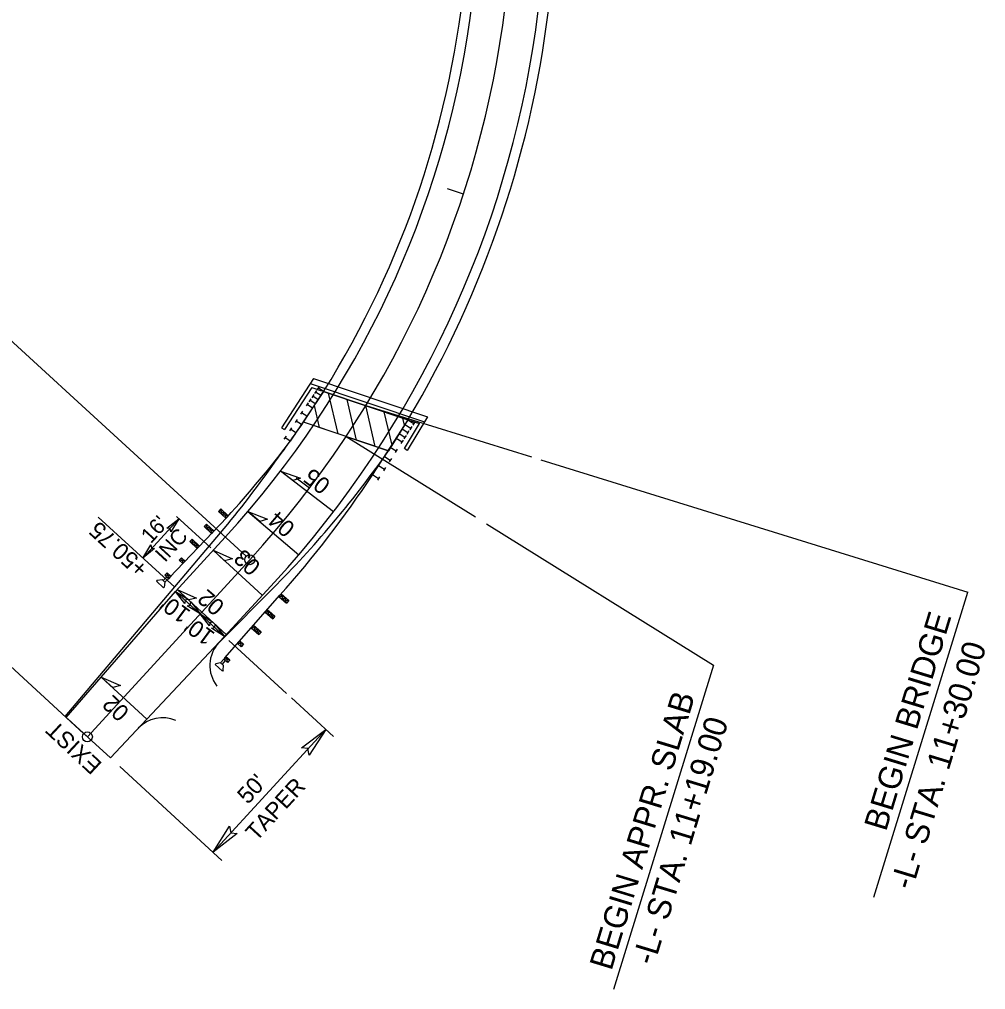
# Model space of a CAD drawing. Extents: x 1348352 to 1349119, y 1028998 to 1029749.
# Drawn here: x 1348729 to 1349018.8, y 1028998.5 to 1029289.4 of the extents above; entities that cross this region are included whole.
import ezdxf

# ---------------------------------------------------------------- set-up
doc = ezdxf.new("R2010")
doc.units = 0
for name, color, linetype in [('Default', 7, 'Continuous'), ('Prop Dimension', 7, 'Continuous'), ('Prop Dimension Text', 7, 'Continuous'), ('Prop DSN Text', 7, 'Continuous'), ('Prop EOT', 7, 'Continuous'), ('Prop Guardrail', 7, 'Continuous'), ('Prop Guardrail Anchor Unit CELL', 7, 'Continuous'), ('Prop Horizontal Alignment', 7, 'Continuous'), ('Prop Horizontal Alignment Station Label', 7, 'Continuous'), ('Prop Horizontal Alignment Tick Large', 7, 'Continuous'), ('Prop Horizontal Alignment Tick Small', 7, 'Continuous'), ('Prop Leader Line Medium', 7, 'Continuous'), ('Prop Paved Shoulder', 7, 'Continuous'), ('Prop Roadway Bridge', 7, 'Continuous'), ('Prop Structure Anchor Unit CELL', 7, 'Continuous'), ('Prop Superelevation  Arrow CELL', 7, 'Continuous'), ('Prop Superelevation Label', 7, 'Continuous'), ('Prop Terminator CELL', 7, 'Continuous')]:
    doc.layers.add(name, color=color, linetype=linetype)

msp = doc.modelspace()

# ---------------------------------------------------------------- linework, layer by layer
at = {"layer": 'Default'}
for p, q in [((1348817.21, 1029181.75), (1348807.64, 1029166.96)), ((1348816.65, 1029179.04), (1348808.46, 1029166.38)), ((1348851.42, 1029170.26), (1348845.3, 1029160.18)), ((1348844.44, 1029160.7), (1348848.99, 1029168.18)), ((1348807.64, 1029166.96), (1348808.46, 1029166.38)), ((1348845.3, 1029160.18), (1348844.44, 1029160.7))]:
    msp.add_line(p, q, dxfattribs=at)
for points in [[(1348817.21, 1029181.75), (1348851.42, 1029170.26)], [(1348816.23, 1029180.24), (1348850.49, 1029168.73)], [(1348816.23, 1029180.24), (1348850.49, 1029168.73)], [(1348816.65, 1029179.04), (1348819.57, 1029178.06)], [(1348845.51, 1029169.35), (1348848.99, 1029168.18)]]:
    msp.add_lwpolyline(points, dxfattribs=at)
at = {"layer": 'Prop Dimension'}
for p, q in [((1348775.56, 1029119.11), (1348752.6, 1029140.17)), ((1348776.79, 1029139.69), (1348765.98, 1029127.9)), ((1348776.06, 1029140.37), (1348786.38, 1029130.9)), ((1348790.53, 1029104.37), (1348775.79, 1029117.88)), ((1348809.12, 1029087.32), (1348791.84, 1029103.17)), ((1348823.22, 1029074.39), (1348810.6, 1029085.96)), ((1348787.09, 1029039.68), (1348820.88, 1029076.53)), ((1348789.75, 1029037.24), (1348759.1, 1029065.35))]:
    msp.add_line(p, q, dxfattribs=at)
at = {"layer": 'Prop EOT'}
for p, q in [((1348775.79, 1029117.88), (1348790.71, 1029134.15)), ((1348790.53, 1029104.37), (1348805.45, 1029120.64)), ((1348743.04, 1029080.07), (1348775.79, 1029117.88)), ((1348756.28, 1029067.94), (1348790.53, 1029104.37)), ((1348756.28, 1029067.94), (1348743.04, 1029080.07))]:
    msp.add_line(p, q, dxfattribs=at)
for centre, radius, start, end in [((1348576.98, 1029330.16), 310, 317.4777, 26.2288), ((1348576.98, 1029330.16), 290, 317.4777, 26.2288), ((1348796.1, 1029095.69), 10, 136.7575, 218.2791), ((1348771.93, 1029069.99), 10, 66.6994, 136.7575)]:
    msp.add_arc(centre, radius, start, end, dxfattribs=at)
at = {"layer": 'Prop Guardrail'}
for centre, radius, start, end in [((1348579.88, 1029335.52), 287.83, 317.2565, 323.1599), ((1348572.34, 1029326.1), 314.58, 318.2785, 326.5917)]:
    msp.add_arc(centre, radius, start, end, dxfattribs=at)
at = {"layer": 'Prop Guardrail Anchor Unit CELL'}
for p, q in [((1348789.41, 1029142.62), (1348788.72, 1029141.89)), ((1348790.92, 1029139.8), (1348788.72, 1029141.89)), ((1348788.72, 1029141.89), (1348790.51, 1029141.57)), ((1348791.61, 1029140.52), (1348789.41, 1029142.62)), ((1348789.82, 1029140.85), (1348789.41, 1029142.62)), ((1348790.51, 1029141.57), (1348789.82, 1029140.85)), ((1348790.51, 1029141.57), (1348790.92, 1029139.8)), ((1348774.02, 1029122.06), (1348791.26, 1029140.16)), ((1348785.1, 1029138.09), (1348784.41, 1029137.37)), ((1348787.3, 1029136), (1348785.1, 1029138.09)), ((1348785.51, 1029136.32), (1348785.1, 1029138.09)), ((1348791.61, 1029140.52), (1348789.82, 1029140.85)), ((1348791.61, 1029140.52), (1348790.92, 1029139.8)), ((1348786.61, 1029135.27), (1348784.41, 1029137.37)), ((1348784.41, 1029137.37), (1348786.2, 1029137.04)), ((1348786.2, 1029137.04), (1348785.51, 1029136.32)), ((1348787.3, 1029136), (1348785.51, 1029136.32)), ((1348786.2, 1029137.04), (1348786.61, 1029135.27)), ((1348787.3, 1029136), (1348786.61, 1029135.27)), ((1348780.79, 1029133.56), (1348780.1, 1029132.84)), ((1348782.3, 1029130.75), (1348780.1, 1029132.84)), ((1348780.1, 1029132.84), (1348781.89, 1029132.52)), ((1348782.99, 1029131.47), (1348780.79, 1029133.56)), ((1348781.2, 1029131.79), (1348780.79, 1029133.56)), ((1348781.89, 1029132.52), (1348781.2, 1029131.79)), ((1348781.89, 1029132.52), (1348782.3, 1029130.75)), ((1348782.99, 1029131.47), (1348781.2, 1029131.79)), ((1348782.99, 1029131.47), (1348782.3, 1029130.75)), ((1348777.58, 1029127.99), (1348776.89, 1029127.27)), ((1348777.99, 1029126.22), (1348776.89, 1029127.27)), ((1348778.68, 1029126.94), (1348776.89, 1029127.27)), ((1348778.68, 1029126.94), (1348777.58, 1029127.99)), ((1348777.58, 1029127.99), (1348777.99, 1029126.22)), ((1348778.68, 1029126.94), (1348777.99, 1029126.22)), ((1348773.27, 1029123.47), (1348772.58, 1029122.74)), ((1348774.37, 1029122.42), (1348773.27, 1029123.47)), ((1348773.27, 1029123.46), (1348773.68, 1029121.69)), ((1348770.34, 1029121.22), (1348770.13, 1029121)), ((1348772.25, 1029118.97), (1348770.13, 1029121)), ((1348770.34, 1029121.22), (1348771.77, 1029121.48)), ((1348771.77, 1029121.48), (1348772.65, 1029120.64)), ((1348772.13, 1029121.13), (1348773.15, 1029122.2)), ((1348772.65, 1029120.64), (1348772.46, 1029119.19)), ((1348773.68, 1029121.69), (1348772.58, 1029122.74)), ((1348774.37, 1029122.42), (1348772.58, 1029122.74)), ((1348773.67, 1029121.7), (1348772.65, 1029120.64)), ((1348774.37, 1029122.42), (1348773.68, 1029121.69)), ((1348772.46, 1029119.19), (1348772.25, 1029118.97)), ((1348790.61, 1029097.98), (1348807.14, 1029116.74)), ((1348807.47, 1029117.12), (1348806.81, 1029116.37)), ((1348806.81, 1029116.37), (1348809.09, 1029114.36)), ((1348808.61, 1029116.11), (1348806.81, 1029116.37)), ((1348807.47, 1029117.12), (1348809.75, 1029115.11)), ((1348807.47, 1029117.12), (1348807.95, 1029115.36)), ((1348808.61, 1029116.11), (1348807.95, 1029115.36)), ((1348807.95, 1029115.36), (1348809.75, 1029115.11)), ((1348809.09, 1029114.36), (1348808.61, 1029116.11)), ((1348809.75, 1029115.11), (1348809.09, 1029114.36)), ((1348803.34, 1029112.43), (1348802.68, 1029111.68)), ((1348803.34, 1029112.43), (1348805.62, 1029110.42)), ((1348803.34, 1029112.43), (1348803.82, 1029110.67)), ((1348802.68, 1029111.68), (1348804.96, 1029109.67)), ((1348804.48, 1029111.42), (1348802.68, 1029111.68)), ((1348804.48, 1029111.42), (1348803.82, 1029110.67)), ((1348803.82, 1029110.67), (1348805.62, 1029110.42)), ((1348804.96, 1029109.67), (1348804.48, 1029111.42)), ((1348805.62, 1029110.42), (1348804.96, 1029109.67)), ((1348799.21, 1029107.74), (1348798.55, 1029106.99)), ((1348798.55, 1029106.99), (1348800.82, 1029104.98)), ((1348800.35, 1029106.73), (1348798.55, 1029106.99)), ((1348799.21, 1029107.74), (1348801.48, 1029105.73)), ((1348799.21, 1029107.74), (1348799.68, 1029105.98)), ((1348800.35, 1029106.73), (1348799.68, 1029105.98)), ((1348799.68, 1029105.98), (1348801.48, 1029105.73)), ((1348800.82, 1029104.98), (1348800.35, 1029106.73)), ((1348801.48, 1029105.73), (1348800.82, 1029104.98)), ((1348795.08, 1029103.05), (1348794.41, 1029102.3)), ((1348794.41, 1029102.3), (1348795.55, 1029101.29)), ((1348796.21, 1029102.04), (1348794.41, 1029102.3)), ((1348795.08, 1029103.05), (1348796.22, 1029102.04)), ((1348795.08, 1029103.05), (1348795.55, 1029101.29)), ((1348796.22, 1029102.04), (1348795.55, 1029101.29)), ((1348790.29, 1029097.6), (1348789.32, 1029096.49)), ((1348790.94, 1029098.36), (1348790.28, 1029097.61)), ((1348790.28, 1029097.61), (1348791.42, 1029096.6)), ((1348792.08, 1029097.35), (1348790.28, 1029097.61)), ((1348790.94, 1029098.36), (1348792.08, 1029097.35)), ((1348790.94, 1029098.36), (1348791.42, 1029096.6)), ((1348792.08, 1029097.35), (1348791.42, 1029096.6)), ((1348787.9, 1029096.18), (1348787.7, 1029095.95)), ((1348787.7, 1029095.95), (1348789.9, 1029094.01)), ((1348789.32, 1029096.49), (1348787.9, 1029096.18)), ((1348790.24, 1029095.69), (1348789.32, 1029096.49)), ((1348789.86, 1029096.02), (1348790.83, 1029097.12)), ((1348790.11, 1029094.24), (1348790.24, 1029095.69)), ((1348790.11, 1029094.24), (1348789.9, 1029094.01))]:
    msp.add_line(p, q, dxfattribs=at)
at = {"layer": 'Prop Horizontal Alignment'}
msp.add_line((1348749.37, 1029074.27), (1348798.08, 1029127.4), dxfattribs=at)
msp.add_arc((1348576.98, 1029330.16), 300, 317.4777, 26.2288, dxfattribs=at)
at = {"layer": 'Prop Horizontal Alignment Station Label'}
for p, q in [((1348796.98, 1029128.41), (1348569.31, 1029337.19)), ((1348748.26, 1029075.29), (1348517.58, 1029286.83))]:
    msp.add_line(p, q, dxfattribs=at)
for centre in [(1348798.08, 1029127.4), (1348749.37, 1029074.27)]:
    msp.add_circle(centre, 1.5, dxfattribs=at)
at = {"layer": 'Prop Horizontal Alignment Tick Large'}
msp.add_line((1348749.37, 1029074.27), (1348743.47, 1029079.68), dxfattribs=at)
at = {"layer": 'Prop Horizontal Alignment Tick Small'}
for p, q in [((1348862.15, 1029237), (1348857.4, 1029238.55)), ((1348815.97, 1029148.82), (1348811.99, 1029151.84))]:
    msp.add_line(p, q, dxfattribs=at)
at = {"layer": 'Prop Leader Line Medium'}
for p, q in [((1348832.88, 1029173.59), (1348882.55, 1029158.2)), ((1348826.97, 1029164.31), (1348865.74, 1029140.2)), ((1348885.39, 1029157.32), (1349013.44, 1029117.66)), ((1348869.03, 1029138.15), (1348937.13, 1029095.78)), ((1348985.27, 1029026.21), (1349013.44, 1029117.66)), ((1348937.13, 1029095.78), (1348907.17, 1028998.5))]:
    msp.add_line(p, q, dxfattribs=at)
at = {"layer": 'Prop Paved Shoulder'}
for p, q in [((1348742.74, 1029080.36), (1348789.33, 1029135.43)), ((1348806.18, 1029119.97), (1348788.39, 1029102.06))]:
    msp.add_line(p, q, dxfattribs=at)
for centre, radius, start, end in [((1348576.98, 1029330.16), 287, 322.8105, 325.7431), ((1348584.68, 1029339.37), 311.77, 315.2732, 324.8851), ((1348569.71, 1029320.62), 287.27, 319.8605, 325.2032)]:
    msp.add_arc(centre, radius, start, end, dxfattribs=at)
at = {"layer": 'Prop Roadway Bridge'}
for p, q in [((1348845.51, 1029169.35), (1348820.22, 1029177.84)), ((1348824.56, 1029165.12), (1348821.72, 1029177.34)), ((1348818.99, 1029166.99), (1348817.46, 1029173.6)), ((1348830.13, 1029163.25), (1348827.29, 1029175.47)), ((1348835.69, 1029161.38), (1348832.86, 1029173.6)), ((1348840.75, 1029161.71), (1348838.42, 1029171.73)), ((1348826.97, 1029164.31), (1348814.19, 1029168.6)), ((1348844.49, 1029167.71), (1348843.99, 1029169.86)), ((1348826.97, 1029164.31), (1348839.71, 1029160.03))]:
    msp.add_line(p, q, dxfattribs=at)
msp.add_lwpolyline([(1348820.22, 1029177.84), (1348845.51, 1029169.35), (1348839.71, 1029160.03), (1348814.19, 1029168.6)], close=True, dxfattribs=at)
for radius, start, end in [(287, 327.9438, 354.9179), (313, 329.0842, 353.7791)]:
    msp.add_arc((1348576.98, 1029330.16), radius, start, end, dxfattribs=at)
at = {"layer": 'Prop Structure Anchor Unit CELL'}
for p, q in [((1348818.94, 1029179.36), (1348818.33, 1029178.45)), ((1348820.22, 1029177.84), (1348818.63, 1029178.9)), ((1348820.22, 1029177.84), (1348810.23, 1029162.94)), ((1348817.27, 1029176.88), (1348816.66, 1029175.97)), ((1348818.56, 1029175.36), (1348816.97, 1029176.42)), ((1348818.11, 1029178.12), (1348817.5, 1029177.21)), ((1348819.39, 1029176.6), (1348817.8, 1029177.66)), ((1348815.61, 1029174.39), (1348815, 1029173.48)), ((1348816.89, 1029172.87), (1348815.3, 1029173.94)), ((1348816.44, 1029175.64), (1348815.83, 1029174.72)), ((1348817.73, 1029174.11), (1348816.14, 1029175.18)), ((1348813.94, 1029171.91), (1348813.33, 1029171)), ((1348815.23, 1029170.39), (1348813.64, 1029171.46)), ((1348812.28, 1029169.43), (1348811.67, 1029168.52)), ((1348813.56, 1029167.91), (1348811.97, 1029168.97)), ((1348845.51, 1029169.35), (1348834.94, 1029152.89)), ((1348844.63, 1029167.97), (1348846.38, 1029166.85)), ((1348845.51, 1029169.35), (1348847.26, 1029168.22)), ((1348846.71, 1029167.35), (1348846.06, 1029166.34)), ((1348847.59, 1029168.72), (1348846.94, 1029167.72)), ((1348808.95, 1029164.46), (1348808.34, 1029163.55)), ((1348810.61, 1029166.94), (1348810, 1029166.03)), ((1348811.9, 1029165.42), (1348810.31, 1029166.49)), ((1348842.87, 1029165.23), (1348844.62, 1029164.1)), ((1348843.75, 1029166.6), (1348845.5, 1029165.48)), ((1348844.95, 1029164.61), (1348844.3, 1029163.6)), ((1348845.83, 1029165.98), (1348845.18, 1029164.97)), ((1348810.23, 1029162.94), (1348808.64, 1029164.01)), ((1348841.99, 1029163.86), (1348843.74, 1029162.73)), ((1348844.06, 1029163.24), (1348843.42, 1029162.23)), ((1348838.46, 1029158.37), (1348840.22, 1029157.25)), ((1348840.23, 1029161.12), (1348841.98, 1029159.99)), ((1348842.3, 1029160.49), (1348841.66, 1029159.49)), ((1348836.7, 1029155.63), (1348838.46, 1029154.5)), ((1348840.54, 1029157.75), (1348839.9, 1029156.74)), ((1348834.94, 1029152.89), (1348836.7, 1029151.76)), ((1348838.78, 1029155.01), (1348838.14, 1029154)), ((1348837.02, 1029152.26), (1348836.37, 1029151.26))]:
    msp.add_line(p, q, dxfattribs=at)
at = {"layer": 'Prop Superelevation  Arrow CELL'}
for p, q in [((1348823.16, 1029141.75), (1348807.27, 1029153.91)), ((1348797.55, 1029141.88), (1348812.76, 1029128.9)), ((1348801.85, 1029116.71), (1348787.11, 1029130.23)), ((1348776.3, 1029118.44), (1348791.04, 1029104.92)), ((1348767.24, 1029079.6), (1348753.52, 1029092.17))]:
    msp.add_line(p, q, dxfattribs=at)
for points in [[(1348807.27, 1029153.91), (1348813.25, 1029151.85), (1348810.95, 1029151.09)], [(1348797.55, 1029141.88), (1348803.41, 1029139.51), (1348801.07, 1029138.88)], [(1348787.11, 1029130.23), (1348792.89, 1029127.65), (1348790.52, 1029127.1)], [(1348776.3, 1029118.44), (1348782.07, 1029115.85), (1348779.71, 1029115.31)], [(1348753.52, 1029092.17), (1348759.35, 1029089.71), (1348756.99, 1029089.12)]]:
    msp.add_lwpolyline(points, close=True, dxfattribs=at)
at = {"layer": 'Prop Terminator CELL'}
for points in [[(1348773.23, 1029136.84), (1348776.79, 1029139.69), (1348774.39, 1029135.77), (1348774.17, 1029136.74)], [(1348769.54, 1029130.76), (1348765.98, 1029127.9), (1348768.38, 1029131.82), (1348768.6, 1029130.86)], [(1348778.58, 1029114.27), (1348775.79, 1029117.88), (1348779.67, 1029115.41), (1348778.7, 1029115.21)], [(1348780.37, 1029114.74), (1348783.17, 1029111.13), (1348779.29, 1029113.59), (1348780.25, 1029113.8)], [(1348785.96, 1029107.52), (1348783.17, 1029111.13), (1348787.04, 1029108.66), (1348786.08, 1029108.46)], [(1348787.74, 1029107.98), (1348790.53, 1029104.37), (1348786.65, 1029106.83), (1348787.62, 1029107.03)], [(1348813.62, 1029070.99), (1348820.88, 1029076.53), (1348815.9, 1029068.81), (1348815.51, 1029070.74)], [(1348794.29, 1029045.29), (1348787.09, 1029039.68), (1348792, 1029047.45), (1348792.41, 1029045.52)]]:
    msp.add_lwpolyline(points, close=True, dxfattribs=at)

# ---------------------------------------------------------------- texts
at = {"layer": 'Prop Dimension'}
for s, height, rotation, p in [('+50.75', 5, 137.4777, (1348768.01, 1029125.29)), ("16'", 4.608, 47.4777, (1348768.41, 1029132)), ('INC', 4.608, 47.4777, (1348772.63, 1029126.38))]:
    msp.add_text(s, height=height, rotation=rotation, dxfattribs=at).set_placement(p)
at = {"layer": 'Prop Dimension Text'}
for s, rotation, p in [("10'", 143.5301, (1348780.65, 1029111.9)), ("10'", 143.5301, (1348787.96, 1029105.27)), (" 50'", 47.4777, (1348796.27, 1029052.45)), (' TAPER', 47.4777, (1348798.81, 1029041.35))]:
    msp.add_text(s, height=5, rotation=rotation, dxfattribs=at).set_placement(p)
at = {"layer": 'Prop DSN Text'}
for s, p in [('BEGIN BRIDGE', (1348988.89, 1029045.69)), ('-L- STA. 11+30.00', (1348996.76, 1029028.09)), ('BEGIN APPR. SLAB', (1348906.54, 1029003.94)), ('-L- STA. 11+19.00', (1348919.36, 1029005.47))]:
    msp.add_text(s, height=7, rotation=73.074, dxfattribs=at).set_placement(p)
at = {"layer": 'Prop Superelevation Label'}
for s, rotation, p in [('05', 142.5718, (1348822.67, 1029150.6)), ('04', 139.516, (1348812.02, 1029137.5)), ('03', 137.4777, (1348801.7, 1029125.87)), ('02', 139.3898, (1348790.88, 1029114.01)), ('02', 136.9056, (1348762.29, 1029082.11)), ('EXIST', 136.9056, (1348754.08, 1029066.25))]:
    msp.add_text(s, height=5, rotation=rotation, dxfattribs=at).set_placement(p)

doc.saveas('drawing.dxf')
